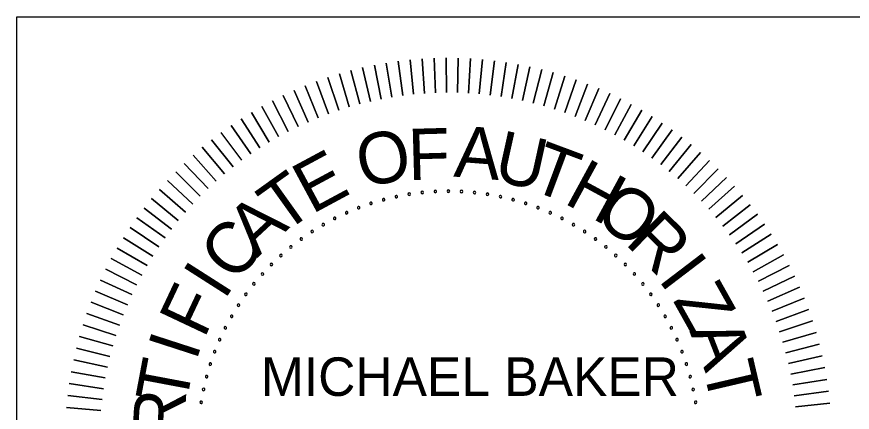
# Model space of a CAD drawing. Extents: x -984 to 3998, y 83 to 2143.
# Drawn here: x 2730.1 to 3001.2, y 360.3 to 488.7 of the extents above; entities that cross this region are included whole.
import ezdxf

# ---------------------------------------------------------------- set-up
doc = ezdxf.new("R2010")
doc.units = 0
doc.layers.add('Level 55', color=7, linetype='Continuous')
doc.layers.add('Level 57', color=7, linetype='Continuous')

msp = doc.modelspace()

# ---------------------------------------------------------------- linework, layer by layer
at = {"layer": 'Level 55'}
for points in [[(2858.9, 463.5), (2857.78, 474.67)], [(2857.78, 474.67), (2858.9, 463.5)], [(2862.44, 463.8), (2861.68, 475)], [(2861.68, 475), (2862.44, 463.8)], [(2865.99, 463.99), (2865.58, 475.2)], [(2865.58, 475.2), (2865.99, 463.99)], [(2869.55, 464.06), (2869.49, 475.28)], [(2869.49, 475.28), (2869.55, 464.06)], [(2873.11, 464.03), (2873.4, 475.24)], [(2873.4, 475.24), (2873.11, 464.03)], [(2876.66, 463.88), (2877.3, 475.08)], [(2877.3, 475.08), (2876.66, 463.88)], [(2880.21, 463.62), (2881.2, 474.8)], [(2881.2, 474.8), (2880.21, 463.62)], [(2844.87, 461.2), (2842.36, 472.14)], [(2842.36, 472.14), (2844.87, 461.2)], [(2848.35, 461.94), (2846.18, 472.95)], [(2846.18, 472.95), (2848.35, 461.94)], [(2851.85, 462.57), (2850.03, 473.64)], [(2850.03, 473.64), (2851.85, 462.57)], [(2855.37, 463.09), (2853.9, 474.22)], [(2853.9, 474.22), (2855.37, 463.09)], [(2883.74, 463.25), (2885.09, 474.39)], [(2885.09, 474.39), (2883.74, 463.25)], [(2887.27, 462.77), (2888.96, 473.86)], [(2888.96, 473.86), (2887.27, 462.77)], [(2890.78, 462.18), (2892.82, 473.21)], [(2892.82, 473.21), (2890.78, 462.18)], [(2894.26, 461.47), (2896.65, 472.44)], [(2896.65, 472.44), (2894.26, 461.47)], [(2837.99, 459.39), (2834.8, 470.15)], [(2834.8, 470.15), (2837.99, 459.39)], [(2841.41, 460.35), (2838.56, 471.2)], [(2838.56, 471.2), (2841.41, 460.35)], [(2897.73, 460.66), (2900.46, 471.55)], [(2900.46, 471.55), (2897.73, 460.66)], [(2901.16, 459.74), (2904.23, 470.54)], [(2904.23, 470.54), (2901.16, 459.74)], [(2904.57, 458.72), (2907.98, 469.41)], [(2907.98, 469.41), (2904.57, 458.72)], [(2831.24, 457.16), (2827.38, 467.69)], [(2827.38, 467.69), (2831.24, 457.16)], [(2834.59, 458.33), (2831.07, 468.98)], [(2831.07, 468.98), (2834.59, 458.33)], [(2907.94, 457.58), (2911.68, 468.16)], [(2911.68, 468.16), (2907.94, 457.58)], [(2911.27, 456.34), (2915.35, 466.8)], [(2915.35, 466.8), (2911.27, 456.34)], [(2824.64, 454.5), (2820.12, 464.77)], [(2820.12, 464.77), (2824.64, 454.5)], [(2827.92, 455.88), (2823.73, 466.29)], [(2823.73, 466.29), (2827.92, 455.88)], [(2914.57, 455), (2918.97, 465.33)], [(2918.97, 465.33), (2914.57, 455)], [(2917.82, 453.56), (2922.54, 463.74)], [(2922.54, 463.74), (2917.82, 453.56)], [(2818.22, 451.44), (2813.07, 461.41)], [(2813.07, 461.41), (2818.22, 451.44)], [(2821.4, 453.02), (2816.57, 463.15)], [(2816.57, 463.15), (2821.4, 453.02)], [(2921.02, 452.01), (2926.06, 462.04)], [(2926.06, 462.04), (2921.02, 452.01)], [(2815.09, 449.75), (2809.62, 459.56)], [(2809.62, 459.56), (2815.09, 449.75)], [(2924.17, 450.36), (2929.52, 460.23)], [(2929.52, 460.23), (2924.17, 450.36)], [(2927.27, 448.62), (2932.93, 458.31)], [(2932.93, 458.31), (2927.27, 448.62)], [(2808.98, 446.1), (2802.92, 455.54)], [(2802.92, 455.54), (2808.98, 446.1)], [(2812.01, 447.97), (2806.24, 457.6)], [(2806.24, 457.6), (2812.01, 447.97)], [(2930.31, 446.78), (2936.27, 456.28)], [(2936.27, 456.28), (2930.31, 446.78)], [(2806.02, 444.13), (2799.66, 453.38)], [(2799.66, 453.38), (2806.02, 444.13)], [(2933.3, 444.84), (2939.55, 454.16)], [(2939.55, 454.16), (2933.3, 444.84)], [(2803.12, 442.07), (2796.48, 451.11)], [(2936.22, 442.81), (2942.76, 451.93)], [(2942.76, 451.93), (2936.22, 442.81)], [(2800.29, 439.92), (2793.36, 448.75)], [(2793.36, 448.75), (2800.29, 439.92)], [(2939.07, 440.69), (2945.9, 449.6)], [(2945.9, 449.6), (2939.07, 440.69)], [(2797.53, 437.68), (2790.33, 446.29)], [(2790.33, 446.29), (2797.53, 437.68)], [(2941.86, 438.48), (2948.97, 447.17)], [(2948.97, 447.17), (2941.86, 438.48)], [(2794.84, 435.35), (2787.37, 443.73)], [(2787.37, 443.73), (2794.84, 435.35)], [(2944.58, 436.19), (2951.95, 444.65)], [(2951.95, 444.65), (2944.58, 436.19)], [(2954.86, 442.03), (2947.22, 433.81)], [(2947.22, 433.81), (2954.86, 442.03)], [(2792.22, 432.94), (2784.49, 441.08)], [(2784.49, 441.08), (2792.22, 432.94)], [(2957.68, 439.33), (2949.79, 431.35)], [(2949.79, 431.35), (2957.68, 439.33)], [(2789.68, 430.46), (2781.7, 438.35)], [(2781.7, 438.35), (2789.68, 430.46)], [(2787.22, 427.89), (2778.99, 435.52)], [(2778.99, 435.52), (2787.22, 427.89)], [(2960.42, 436.54), (2952.28, 428.81)], [(2952.28, 428.81), (2960.42, 436.54)], [(2784.84, 425.24), (2776.38, 432.62)], [(2776.38, 432.62), (2784.84, 425.24)], [(2963.07, 433.66), (2954.69, 426.19)], [(2954.69, 426.19), (2963.07, 433.66)], [(2782.54, 422.53), (2773.86, 429.63)], [(2773.86, 429.63), (2782.54, 422.53)], [(2965.62, 430.7), (2957.01, 423.5)], [(2957.01, 423.5), (2965.62, 430.7)], [(2780.34, 419.74), (2771.43, 426.57)], [(2771.43, 426.57), (2780.34, 419.74)], [(2968.08, 427.66), (2959.25, 420.74)], [(2959.25, 420.74), (2968.08, 427.66)], [(2778.22, 416.88), (2769.1, 423.43)], [(2769.1, 423.43), (2778.22, 416.88)], [(2970.45, 424.55), (2961.4, 417.9)], [(2961.4, 417.9), (2970.45, 424.55)], [(2972.71, 421.36), (2963.47, 415)], [(2963.47, 415), (2972.71, 421.36)], [(2776.19, 413.96), (2766.87, 420.22)], [(2766.87, 420.22), (2776.19, 413.96)], [(2974.88, 418.11), (2965.44, 412.04)], [(2965.44, 412.04), (2974.88, 418.11)], [(2774.25, 410.98), (2764.74, 416.94)], [(2764.74, 416.94), (2774.25, 410.98)], [(2772.41, 407.93), (2762.72, 413.59)], [(2762.72, 413.59), (2772.41, 407.93)], [(2976.94, 414.79), (2967.31, 409.02)], [(2967.31, 409.02), (2976.94, 414.79)], [(2770.66, 404.84), (2760.8, 410.19)], [(2760.8, 410.19), (2770.66, 404.84)], [(2978.89, 411.4), (2969.09, 405.94)], [(2969.09, 405.94), (2978.89, 411.4)], [(2980.74, 407.96), (2970.77, 402.81)], [(2970.77, 402.81), (2980.74, 407.96)], [(2769.02, 401.68), (2758.99, 406.72)], [(2758.99, 406.72), (2769.02, 401.68)], [(2982.48, 404.46), (2972.35, 399.62)], [(2972.35, 399.62), (2982.48, 404.46)], [(2767.47, 398.48), (2757.29, 403.2)], [(2757.29, 403.2), (2767.47, 398.48)], [(2766.03, 395.23), (2755.7, 399.63)], [(2755.7, 399.63), (2766.03, 395.23)], [(2984.11, 400.9), (2973.84, 396.39)], [(2973.84, 396.39), (2984.11, 400.9)], [(2764.68, 391.94), (2754.22, 396.01)], [(2754.22, 396.01), (2764.68, 391.94)], [(2985.63, 397.3), (2975.22, 393.11)], [(2975.22, 393.11), (2985.63, 397.3)], [(2987.03, 393.65), (2976.49, 389.79)], [(2976.49, 389.79), (2987.03, 393.65)], [(2763.44, 388.6), (2752.86, 392.35)], [(2752.86, 392.35), (2763.44, 388.6)], [(2762.31, 385.23), (2751.62, 388.64)], [(2751.62, 388.64), (2762.31, 385.23)], [(2988.32, 389.96), (2977.66, 386.43)], [(2977.66, 386.43), (2988.32, 389.96)], [(2989.49, 386.23), (2978.73, 383.04)], [(2978.73, 383.04), (2989.49, 386.23)], [(2761.28, 381.83), (2750.49, 384.9)], [(2750.49, 384.9), (2761.28, 381.83)], [(2990.54, 382.46), (2979.68, 379.61)], [(2979.68, 379.61), (2990.54, 382.46)], [(2760.36, 378.39), (2749.48, 381.12)], [(2749.48, 381.12), (2760.36, 378.39)], [(2759.55, 374.93), (2748.59, 377.31)], [(2748.59, 377.31), (2759.55, 374.93)], [(2991.47, 378.67), (2980.53, 376.16)], [(2980.53, 376.16), (2991.47, 378.67)], [(2992.29, 374.84), (2981.27, 372.68)], [(2981.27, 372.68), (2992.29, 374.84)], [(2758.85, 371.44), (2747.82, 373.48)], [(2747.82, 373.48), (2758.85, 371.44)], [(2758.26, 367.93), (2747.17, 369.63)], [(2747.17, 369.63), (2758.26, 367.93)], [(2992.98, 371), (2981.91, 369.18)], [(2981.91, 369.18), (2992.98, 371)], [(2993.55, 367.13), (2982.43, 365.66)], [(2982.43, 365.66), (2993.55, 367.13)], [(2757.78, 364.41), (2746.64, 365.75)], [(2746.64, 365.75), (2757.78, 364.41)], [(2757.41, 360.87), (2746.23, 361.87)], [(2746.23, 361.87), (2757.41, 360.87)], [(2994, 363.25), (2982.84, 362.13)], [(2982.84, 362.13), (2994, 363.25)]]:
    msp.add_lwpolyline(points, dxfattribs=at)
for centre, start, end in [((2857.48, 431.06), 9, 189), ((2857.48, 431.06), 189, 9), ((2861.69, 431.62), 6, 186), ((2861.69, 431.62), 186, 6), ((2865.93, 431.95), 3, 183), ((2865.93, 431.95), 183, 3), ((2870.18, 432.06), 0, 180), ((2870.18, 432.06), 180, 0), ((2874.43, 431.95), 177, 357), ((2874.43, 431.95), 357, 177), ((2878.67, 431.62), 174, 354), ((2878.67, 431.62), 354, 174), ((2882.89, 431.06), 351, 171), ((2882.89, 431.06), 171, 351), ((2845.08, 428.09), 18, 198), ((2849.16, 429.29), 15, 195), ((2849.16, 429.29), 195, 15), ((2853.3, 430.29), 12, 192), ((2853.3, 430.29), 192, 12), ((2887.07, 430.29), 168, 348), ((2887.07, 430.29), 348, 168), ((2891.2, 429.29), 165, 345), ((2891.2, 429.29), 345, 165), ((2895.28, 428.09), 342, 162), ((2841.08, 426.67), 21, 201), ((2841.08, 426.67), 201, 21), ((2845.08, 428.09), 198, 18), ((2895.28, 428.09), 162, 342), ((2899.29, 426.67), 159, 339), ((2899.29, 426.67), 339, 159), ((2833.31, 423.21), 27, 207), ((2833.31, 423.21), 207, 27), ((2837.15, 425.04), 24, 204), ((2837.15, 425.04), 204, 24), ((2903.21, 425.04), 156, 336), ((2903.21, 425.04), 336, 156), ((2907.05, 423.21), 153, 333), ((2907.05, 423.21), 333, 153), ((2829.57, 421.18), 30, 210), ((2829.57, 421.18), 210, 30), ((2910.79, 421.18), 150, 330), ((2910.79, 421.18), 330, 150), ((2825.95, 418.96), 33, 213), ((2825.95, 418.96), 213, 33), ((2914.41, 418.96), 147, 327), ((2914.41, 418.96), 327, 147), ((2822.44, 416.55), 36, 216), ((2822.44, 416.55), 216, 36), ((2917.92, 416.55), 144, 324), ((2917.92, 416.55), 324, 144), ((2819.07, 413.96), 39, 219), ((2819.07, 413.96), 219, 39), ((2921.29, 413.96), 141, 321), ((2921.29, 413.96), 321, 141), ((2815.84, 411.2), 42, 222), ((2815.84, 411.2), 222, 42), ((2924.52, 411.2), 138, 318), ((2924.52, 411.2), 318, 138), ((2812.75, 408.27), 45, 225), ((2812.75, 408.27), 225, 45), ((2927.61, 408.27), 135, 315), ((2927.61, 408.27), 315, 135), ((2809.83, 405.19), 48, 228), ((2809.83, 405.19), 228, 48), ((2930.54, 405.19), 132, 312), ((2930.54, 405.19), 312, 132), ((2807.07, 401.96), 51, 231), ((2807.07, 401.96), 231, 51), ((2933.3, 401.96), 129, 309), ((2933.3, 401.96), 309, 129), ((2804.48, 398.58), 54, 234), ((2804.48, 398.58), 234, 54), ((2935.89, 398.58), 126, 306), ((2935.89, 398.58), 306, 126), ((2802.07, 395.08), 57, 237), ((2802.07, 395.08), 237, 57), ((2938.29, 395.08), 123, 303), ((2938.29, 395.08), 303, 123), ((2799.85, 391.45), 60, 240), ((2799.85, 391.45), 240, 60), ((2940.52, 391.45), 120, 300), ((2940.52, 391.45), 300, 120), ((2797.82, 387.72), 63, 243), ((2797.82, 387.72), 243, 63), ((2942.54, 387.72), 117, 297), ((2942.54, 387.72), 297, 117), ((2795.99, 383.88), 66, 246), ((2795.99, 383.88), 246, 66), ((2944.37, 383.88), 114, 294), ((2944.37, 383.88), 294, 114), ((2794.36, 379.95), 69, 249), ((2794.36, 379.95), 249, 69), ((2946, 379.95), 111, 291), ((2946, 379.95), 291, 111), ((2792.94, 375.94), 72, 252), ((2792.94, 375.94), 252, 72), ((2947.42, 375.94), 108, 288), ((2947.42, 375.94), 288, 108), ((2791.73, 371.87), 75, 255), ((2791.73, 371.87), 255, 75), ((2948.63, 371.87), 105, 285), ((2948.63, 371.87), 285, 105), ((2790.74, 367.73), 78, 258), ((2790.74, 367.73), 258, 78), ((2949.62, 367.73), 102, 282), ((2949.62, 367.73), 282, 102), ((2789.97, 363.55), 81, 261), ((2789.97, 363.55), 261, 81), ((2950.4, 363.55), 99, 279), ((2950.4, 363.55), 279, 99)]:
    msp.add_arc(centre, 0.417, start, end, dxfattribs=at)
at = {"layer": 'Level 57'}
msp.add_lwpolyline([(2730.1, 488.67), (3010.37, 488.67), (3010.37, 212.74), (2730.1, 212.74)], close=True, dxfattribs=at)

# ---------------------------------------------------------------- texts
at = {"layer": 'Level 55'}
for s, rotation, p in [('A', 355.5955, (2871.7, 436.8)), ('O', 10.7295, (2842.02, 433.17)), ('F', 1.5867, (2857.25, 435.58)), ('U', 347.5481, (2884.31, 435.61)), ('T', 339.5007, (2895.95, 432.83)), ('E', 28.279, (2825.84, 424.44)), ('H', 331.4533, (2907.25, 428.38)), ('T', 35.5725, (2816.53, 417.99)), ('O', 323.4059, (2916.82, 423.11)), ('A', 42.8659, (2808.07, 410.28)), ('R', 315.3585, (2927.15, 415.2)), ('C', 50.1594, (2801.06, 401.95)), ('I', 307.3112, (2937.98, 403.46)), ('I', 57.4529, (2797.44, 396.38)), ('F', 64.7464, (2790.89, 383.92)), ('Z', 299.2638, (2942.88, 396.67)), ('I', 72.0398, (2788.31, 376.59)), ('A', 291.2164, (2948.34, 386.65)), ('T', 79.3333, (2785, 362.23)), ('T', 283.169, (2952.7, 374.85)), ('R', 86.6268, (2784.23, 351.21))]:
    msp.add_text(s, height=16.67, rotation=rotation, dxfattribs=at).set_placement(p)
msp.add_text('MICHAEL BAKER', height=12.5016, dxfattribs=at).set_placement((2809.35, 365.62))

doc.saveas('drawing.dxf')
